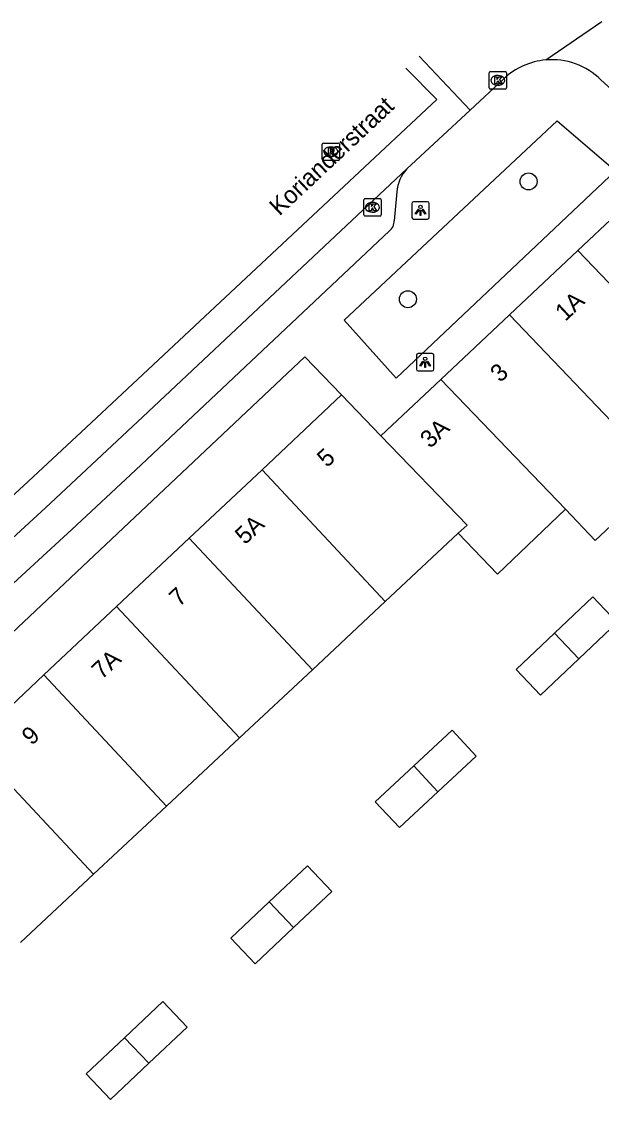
# Model space of a CAD drawing. Extents: x 162542 to 163144, y 380786 to 381511.
# Drawn here: x 162831.4 to 162864.7, y 381446.8 to 381508.8 of the extents above; entities that cross this region are included whole.
import ezdxf

# ---------------------------------------------------------------- set-up
doc = ezdxf.new("R2010")
doc.units = 0
for name, color, linetype in [('IMGEO_Boom', 7, 'Continuous'), ('IMGEO_Fietspad_gesloten', 7, 'Continuous'), ('IMGEO_Kolk', 7, 'Continuous'), ('IMGEO_Lichtpunt', 7, 'Continuous'), ('IMGEO_Openbare_ruimte_label', 7, 'Continuous'), ('IMGEO_Pand', 7, 'Continuous'), ('IMGEO_Pand_nummerreeks', 7, 'Continuous'), ('IMGEO_Rijbaan_lokaal_gesloten', 7, 'Continuous'), ('IMGEO_Rioolput', 7, 'Continuous'), ('IMGEO_Voetpad_open', 7, 'Continuous')]:
    doc.layers.add(name, color=color, linetype=linetype)

msp = doc.modelspace()

# ---------------------------------------------------------------- linework, layer by layer
at = {"layer": 'IMGEO_Boom'}
for centre in [(162860.531, 381499.638), (162853.591, 381492.86)]:
    msp.add_circle(centre, 0.489, dxfattribs=at)
at = {"layer": 'IMGEO_Fietspad_gesloten'}
msp.add_lwpolyline([(162865.722, 381504.554), (162864.695, 381505.488)], dxfattribs=at)
msp.add_arc((162861.873, 381502.628), 4.018, 45.38409, 95.07309, dxfattribs=at)
at = {"layer": 'IMGEO_Kolk'}
for p, q in [((162858.266, 381505.031), (162858.266, 381505.883)), ((162858.341, 381505.957), (162859.193, 381505.957)), ((162858.754, 381505.737), (162858.779, 381505.737)), ((162859.267, 381505.883), (162859.267, 381505.031)), ((162859.193, 381504.957), (162858.341, 381504.957)), ((162858.777, 381505.177), (162858.752, 381505.177)), ((162851.048, 381497.726), (162851.048, 381498.578)), ((162851.123, 381498.652), (162851.975, 381498.652)), ((162851.536, 381498.432), (162851.561, 381498.432)), ((162852.049, 381498.578), (162852.049, 381497.726)), ((162851.975, 381497.652), (162851.123, 381497.652)), ((162851.559, 381497.872), (162851.534, 381497.872))]:
    msp.add_line(p, q, dxfattribs=at)
for points in [[(162858.266, 381505.031), (162858.266, 381505.883)], [(162858.341, 381505.957), (162859.193, 381505.957)], [(162858.587, 381505.657), (162858.71, 381505.657), (162858.71, 381505.506), (162858.84, 381505.657), (162859.004, 381505.657), (162858.858, 381505.506), (162859.011, 381505.257), (162858.859, 381505.257), (162858.774, 381505.421), (162858.71, 381505.354), (162858.71, 381505.257), (162858.587, 381505.257), (162858.587, 381505.657)], [(162859.267, 381505.883), (162859.267, 381505.031)], [(162859.193, 381504.957), (162858.341, 381504.957)], [(162851.048, 381497.726), (162851.048, 381498.578)], [(162851.123, 381498.652), (162851.975, 381498.652)], [(162851.369, 381498.352), (162851.492, 381498.352), (162851.492, 381498.201), (162851.622, 381498.352), (162851.786, 381498.352), (162851.64, 381498.201), (162851.793, 381497.952), (162851.641, 381497.952), (162851.556, 381498.116), (162851.492, 381498.049), (162851.492, 381497.952), (162851.369, 381497.952), (162851.369, 381498.352)], [(162852.049, 381498.578), (162852.049, 381497.726)], [(162851.975, 381497.652), (162851.123, 381497.652)]]:
    msp.add_lwpolyline(points, dxfattribs=at)
for centre, start, end in [((162858.343, 381505.881), 91.55205, 178.44795), ((162858.343, 381505.881), 91.55205, 178.44795), ((162859.191, 381505.881), 1.55205, 88.44795), ((162859.191, 381505.881), 1.55205, 88.44795), ((162858.343, 381505.033), 181.55205, 268.44795), ((162858.343, 381505.033), 181.55205, 268.44795), ((162859.191, 381505.033), 271.55205, 358.44795), ((162859.191, 381505.033), 271.55205, 358.44795), ((162851.125, 381498.576), 91.55205, 178.44795), ((162851.125, 381498.576), 91.55205, 178.44795), ((162851.973, 381498.576), 1.55205, 88.44795), ((162851.973, 381498.576), 1.55205, 88.44795), ((162851.125, 381497.728), 181.55205, 268.44795), ((162851.125, 381497.728), 181.55205, 268.44795), ((162851.973, 381497.728), 271.55205, 358.44795), ((162851.973, 381497.728), 271.55205, 358.44795)]:
    msp.add_arc(centre, 0.0765, start, end, dxfattribs=at)
for centre, major_axis, ratio, start_param, end_param in [((162858.753, 381505.457), (-0.387, 0.002), 0.722429, 4.712389, 7.853982), ((162858.778, 381505.457), (-0.39, 0.002), 0.717154, 1.570796, 4.712389), ((162851.535, 381498.152), (-0.387, 0.002), 0.722429, 4.712389, 7.853982), ((162851.56, 381498.152), (-0.39, 0.002), 0.717154, 1.570796, 4.712389)]:
    msp.add_ellipse(centre, major_axis=major_axis, ratio=ratio, start_param=start_param, end_param=end_param, dxfattribs=at)
at = {"layer": 'IMGEO_Lichtpunt'}
for p, q in [((162853.819, 381498.378), (162853.819, 381497.571)), ((162853.819, 381498.378), (162853.819, 381497.571)), ((162854.721, 381498.473), (162853.913, 381498.473)), ((162854.721, 381498.473), (162853.913, 381498.473)), ((162854.815, 381497.571), (162854.815, 381498.378)), ((162854.815, 381497.571), (162854.815, 381498.378)), ((162853.913, 381497.477), (162854.721, 381497.477)), ((162853.913, 381497.477), (162854.721, 381497.477)), ((162854.085, 381489.639), (162854.085, 381488.832)), ((162854.085, 381489.639), (162854.085, 381488.832)), ((162854.987, 381489.734), (162854.179, 381489.734)), ((162854.987, 381489.734), (162854.179, 381489.734)), ((162855.081, 381488.832), (162855.081, 381489.639)), ((162855.081, 381488.832), (162855.081, 381489.639)), ((162854.179, 381488.738), (162854.987, 381488.738)), ((162854.179, 381488.738), (162854.987, 381488.738))]:
    msp.add_line(p, q, dxfattribs=at)
for points in [[(162854.193, 381498.042), (162854.232, 381498.014), (162854.044, 381497.752), (162854.006, 381497.779), (162854.193, 381498.042)], [(162854.295, 381497.994), (162854.342, 381497.994), (162854.342, 381497.672), (162854.295, 381497.672), (162854.295, 381497.994)], [(162854.405, 381498.014), (162854.443, 381498.041), (162854.63, 381497.779), (162854.591, 381497.751), (162854.405, 381498.014)], [(162854.459, 381489.303), (162854.498, 381489.275), (162854.31, 381489.013), (162854.272, 381489.04), (162854.459, 381489.303)], [(162854.561, 381489.255), (162854.608, 381489.255), (162854.608, 381488.933), (162854.561, 381488.933), (162854.561, 381489.255)], [(162854.671, 381489.275), (162854.709, 381489.302), (162854.896, 381489.04), (162854.857, 381489.012), (162854.671, 381489.275)]]:
    msp.add_lwpolyline(points, dxfattribs=at)
for centre in [(162854.318, 381498.176), (162854.584, 381489.437)]:
    msp.add_circle(centre, 0.0994, dxfattribs=at)
for centre, start, end in [((162853.913, 381498.378), 90, 180), ((162853.913, 381498.378), 90, 180), ((162854.721, 381498.378), 0, 90), ((162854.721, 381498.378), 0, 90), ((162853.913, 381497.571), 180, 270), ((162853.913, 381497.571), 180, 270), ((162854.721, 381497.571), 270, 0), ((162854.721, 381497.571), 270, 360), ((162854.179, 381489.639), 90, 180), ((162854.179, 381489.639), 90, 180), ((162854.987, 381489.639), 0, 90), ((162854.987, 381489.639), 0, 90), ((162854.179, 381488.832), 180, 270), ((162854.179, 381488.832), 180, 270), ((162854.987, 381488.832), 270, 0), ((162854.987, 381488.832), 270, 360)]:
    msp.add_arc(centre, 0.0946, start, end, dxfattribs=at)
at = {"layer": 'IMGEO_Pand'}
for points in [[(162863.362, 381495.663), (162867.774, 381499.816)], [(162859.425, 381491.957), (162863.362, 381495.663)], [(162870.454, 381488.261), (162863.362, 381495.663)], [(162859.425, 381491.957), (162855.488, 381488.251)], [(162866.55, 381484.521), (162859.425, 381491.957)], [(162852.041, 381485.006), (162855.488, 381488.251)], [(162855.488, 381488.251), (162862.646, 381480.78)], [(162845.2, 381483.051), (162849.776, 381487.357)], [(162849.776, 381487.357), (162852.041, 381485.006)], [(162856.485, 381479.395), (162856.991, 381479.868), (162852.041, 381485.006)], [(162866.55, 381484.521), (162868.319, 381482.674), (162864.362, 381478.989), (162862.646, 381480.78)], [(162841.017, 381479.114), (162845.2, 381483.051)], [(162845.2, 381483.051), (162852.291, 381475.471)], [(162862.646, 381480.78), (162858.742, 381477.04), (162856.485, 381479.395)], [(162836.834, 381475.178), (162841.017, 381479.114)], [(162841.017, 381479.114), (162848.096, 381471.547)], [(162856.485, 381479.395), (162852.291, 381475.471)], [(162862.019, 381473.644), (162864.227, 381475.732), (162865.622, 381474.267), (162863.416, 381472.173)], [(162832.651, 381471.242), (162836.834, 381475.178)], [(162836.834, 381475.178), (162843.902, 381467.623)], [(162852.291, 381475.471), (162848.096, 381471.547)], [(162863.416, 381472.173), (162861.209, 381470.079), (162859.813, 381471.558), (162862.019, 381473.644)], [(162863.416, 381472.173), (162862.019, 381473.644)], [(162848.096, 381471.547), (162843.902, 381467.623)], [(162828.467, 381467.306), (162832.651, 381471.242)], [(162832.651, 381471.242), (162839.707, 381463.699)], [(162853.926, 381466.012), (162856.137, 381468.072), (162857.525, 381466.576), (162855.317, 381464.519)], [(162828.467, 381467.306), (162835.513, 381459.775)], [(162843.902, 381467.623), (162839.707, 381463.699)], [(162855.317, 381464.519), (162853.106, 381462.459), (162851.715, 381463.952), (162853.926, 381466.012)], [(162853.926, 381466.012), (162855.317, 381464.519)], [(162839.707, 381463.699), (162835.513, 381459.775)], [(162845.619, 381458.183), (162847.823, 381460.263), (162849.217, 381458.787), (162847.013, 381456.707)], [(162835.513, 381459.775), (162831.318, 381455.851)], [(162847.013, 381456.707), (162844.809, 381454.626), (162843.415, 381456.103), (162845.619, 381458.183)], [(162845.619, 381458.183), (162847.013, 381456.707)], [(162837.297, 381450.374), (162839.499, 381452.452), (162840.893, 381450.976), (162838.689, 381448.898)], [(162838.689, 381448.898), (162836.486, 381446.82), (162835.094, 381448.295), (162837.297, 381450.374)], [(162837.297, 381450.374), (162838.689, 381448.898)]]:
    msp.add_lwpolyline(points, dxfattribs=at)
at = {"layer": 'IMGEO_Rijbaan_lokaal_gesloten'}
for points in [[(162861.518, 381506.63), (162864.749, 381508.84)], [(162854.238, 381506.848), (162857.173, 381503.743)], [(162853.478, 381506.159), (162855.254, 381504.364), (162835.082, 381485.474), (162831.49, 381482.132), (162800.379, 381453.477), (162801.586, 381452.22)], [(162857.173, 381503.743), (162859.109, 381505.542)], [(162853.531, 381500.36), (162857.173, 381503.743)], [(162802.054, 381452.648), (162832.74, 381480.852), (162838.338, 381486.089), (162853.531, 381500.36)]]:
    msp.add_lwpolyline(points, dxfattribs=at)
msp.add_arc((162861.872, 381502.635), 4.011, 95.06779, 133.54385, dxfattribs=at)
at = {"layer": 'IMGEO_Rioolput'}
for p, q in [((162848.66, 381500.924), (162848.66, 381501.776)), ((162848.735, 381501.85), (162849.587, 381501.85)), ((162849.661, 381501.776), (162849.661, 381500.924)), ((162849.148, 381501.63), (162849.173, 381501.63)), ((162849.587, 381500.85), (162848.735, 381500.85)), ((162849.171, 381501.07), (162849.146, 381501.07))]:
    msp.add_line(p, q, dxfattribs=at)
for points in [[(162848.66, 381500.924), (162848.66, 381501.776)], [(162848.735, 381501.85), (162849.587, 381501.85)], [(162849.661, 381501.776), (162849.661, 381500.924)], [(162849.249, 381501.548), (162848.997, 381501.55), (162848.997, 381501.15)], [(162848.997, 381501.15), (162849.121, 381501.15), (162849.121, 381501.312), (162849.132, 381501.312)], [(162849.175, 381501.469), (162849.121, 381501.469), (162849.121, 381501.388)], [(162849.121, 381501.388), (162849.173, 381501.388)], [(162849.179, 381501.283), (162849.25, 381501.15), (162849.39, 381501.15), (162849.325, 381501.276)], [(162849.587, 381500.85), (162848.735, 381500.85)]]:
    msp.add_lwpolyline(points, dxfattribs=at)
for centre, radius, start, end in [((162848.737, 381501.774), 0.0765, 91.55205, 178.44795), ((162848.737, 381501.774), 0.0765, 91.55205, 178.44795), ((162849.585, 381501.774), 0.0765, 1.55205, 88.44795), ((162849.585, 381501.774), 0.0765, 1.55205, 88.44795), ((162849.131, 381501.259), 0.0533, 26.02933, 88.69889), ((162849.157, 381501.577), 0.19, 274.7715, 282.96867), ((162849.181, 381501.373), 0.0964, 77.00612, 93.18647), ((162849.195, 381501.43), 0.0378, 276.66336, 79.67722), ((162849.248, 381501.438), 0.109, 350.36119, 89.41601), ((162849.246, 381501.438), 0.112, 277.58423, 350.98172), ((162849.23, 381501.223), 0.108, 29.51342, 73.79051), ((162848.737, 381500.926), 0.0765, 181.55205, 268.44795), ((162848.737, 381500.926), 0.0765, 181.55205, 268.44795), ((162849.585, 381500.926), 0.0765, 271.55205, 358.44795), ((162849.585, 381500.926), 0.0765, 271.55205, 358.44795)]:
    msp.add_arc(centre, radius, start, end, dxfattribs=at)
for centre, major_axis, ratio, start_param, end_param in [((162849.147, 381501.35), (-0.387, 0.002), 0.722429, 4.712389, 7.853982), ((162849.172, 381501.35), (-0.39, 0.002), 0.717154, 1.570796, 4.712389)]:
    msp.add_ellipse(centre, major_axis=major_axis, ratio=ratio, start_param=start_param, end_param=end_param, dxfattribs=at)
at = {"layer": 'IMGEO_Voetpad_open'}
for points in [[(162862.179, 381503.126), (162865.535, 381500.253), (162852.921, 381488.327), (162849.934, 381491.649), (162862.179, 381503.126)], [(162852.954, 381499.033), (162852.8, 381497.383)], [(162852.532, 381496.794), (162837.92, 381483.037), (162834.262, 381479.623), (162805.706, 381453.35)], [(162818.675, 381462.21), (162847.661, 381489.553), (162849.776, 381487.357)]]:
    msp.add_lwpolyline(points, dxfattribs=at)
for centre, radius, start, end in [((162855.128, 381498.877), 2.18, 137.11239, 175.88733), ((162852.095, 381497.348), 0.705, 308.23167, 2.83645)]:
    msp.add_arc(centre, radius, start, end, dxfattribs=at)

# ---------------------------------------------------------------- texts
at = {"layer": 'IMGEO_Openbare_ruimte_label'}
msp.add_text('Korianderstraat', height=1, rotation=43.17591, dxfattribs=at).set_placement((162846.203, 381497.62))
at = {"layer": 'IMGEO_Pand_nummerreeks'}
for s, rotation, p in [('1A', 43.06924, (162862.637, 381491.551)), ('3', 43.06924, (162858.902, 381488.033)), ('3A', 43.07497, (162854.871, 381484.241)), ('5', 43.06351, (162848.94, 381483.139)), ('5A', 43.06924, (162844.221, 381478.701)), ('7', 43.05778, (162840.43, 381475.13)), ('7A', 43.05778, (162835.979, 381470.946)), ('9', 43.05205, (162831.953, 381467.154))]:
    msp.add_text(s, height=1, rotation=rotation, dxfattribs=at).set_placement(p)

doc.saveas('drawing.dxf')
